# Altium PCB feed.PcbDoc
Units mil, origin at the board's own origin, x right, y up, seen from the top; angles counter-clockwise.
Board outline 1181.1 x 1181.1 mil, 2 copper layers (Top Layer, Bottom Layer); 26 components, 20 nets, 79 pads, 14 vias.
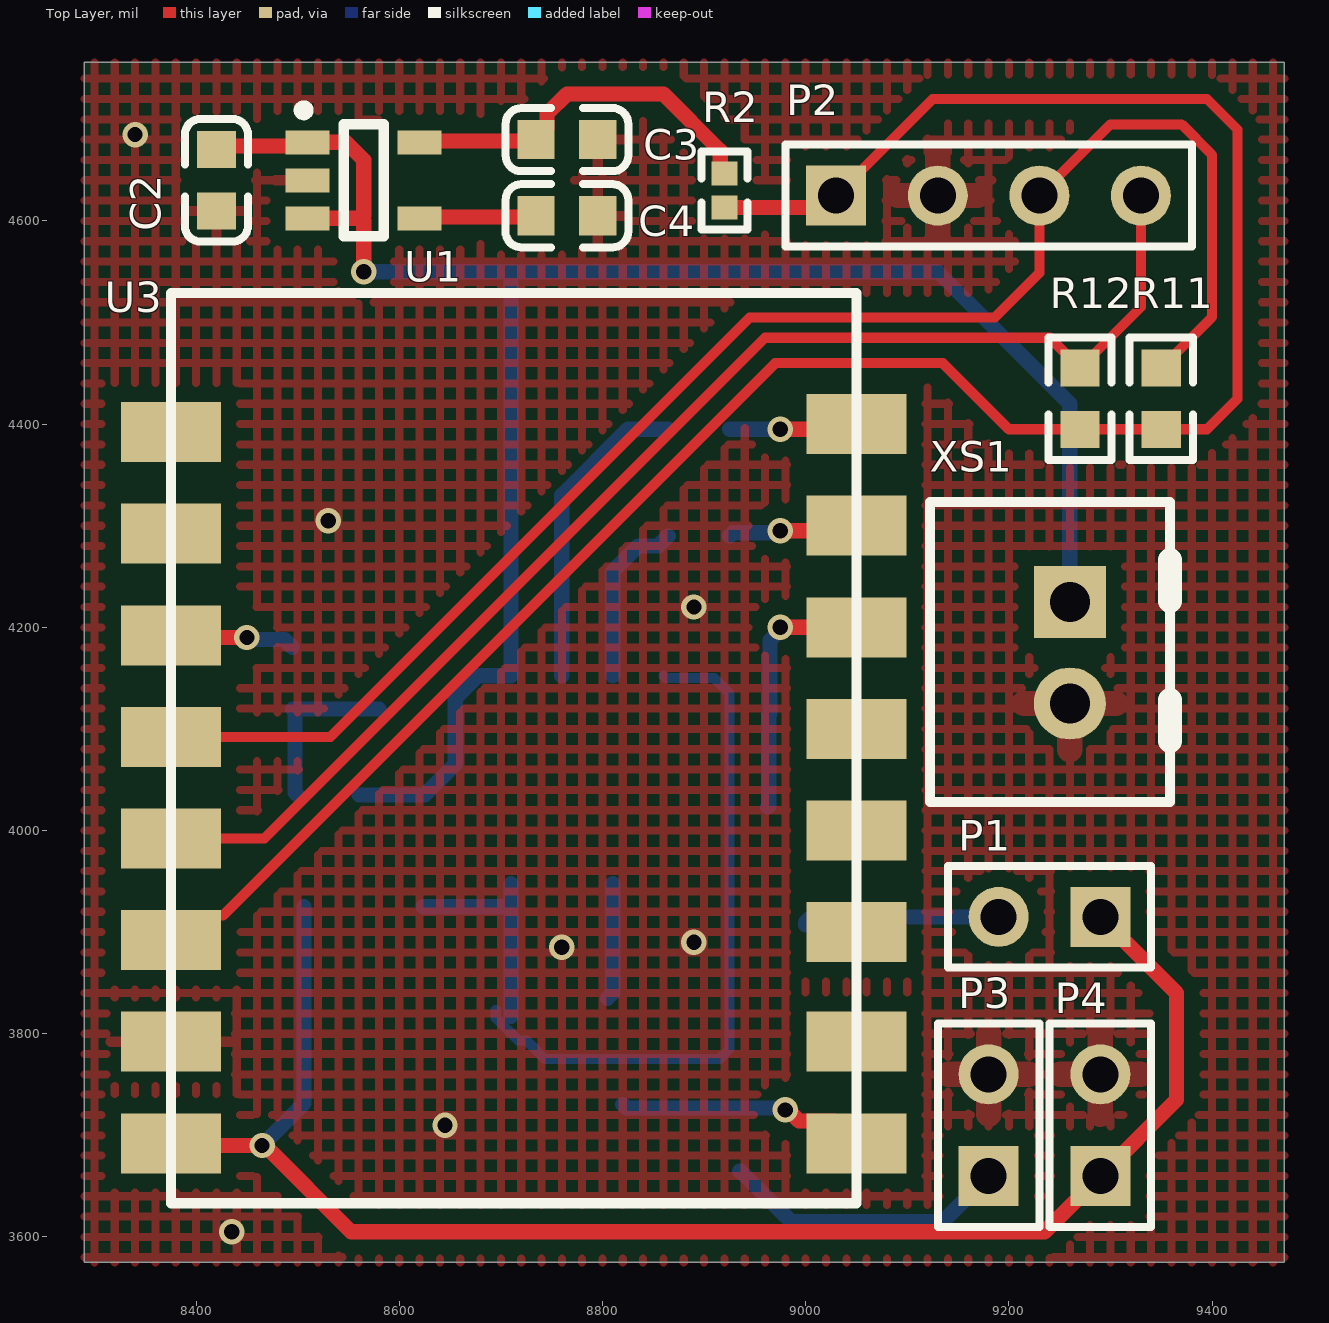
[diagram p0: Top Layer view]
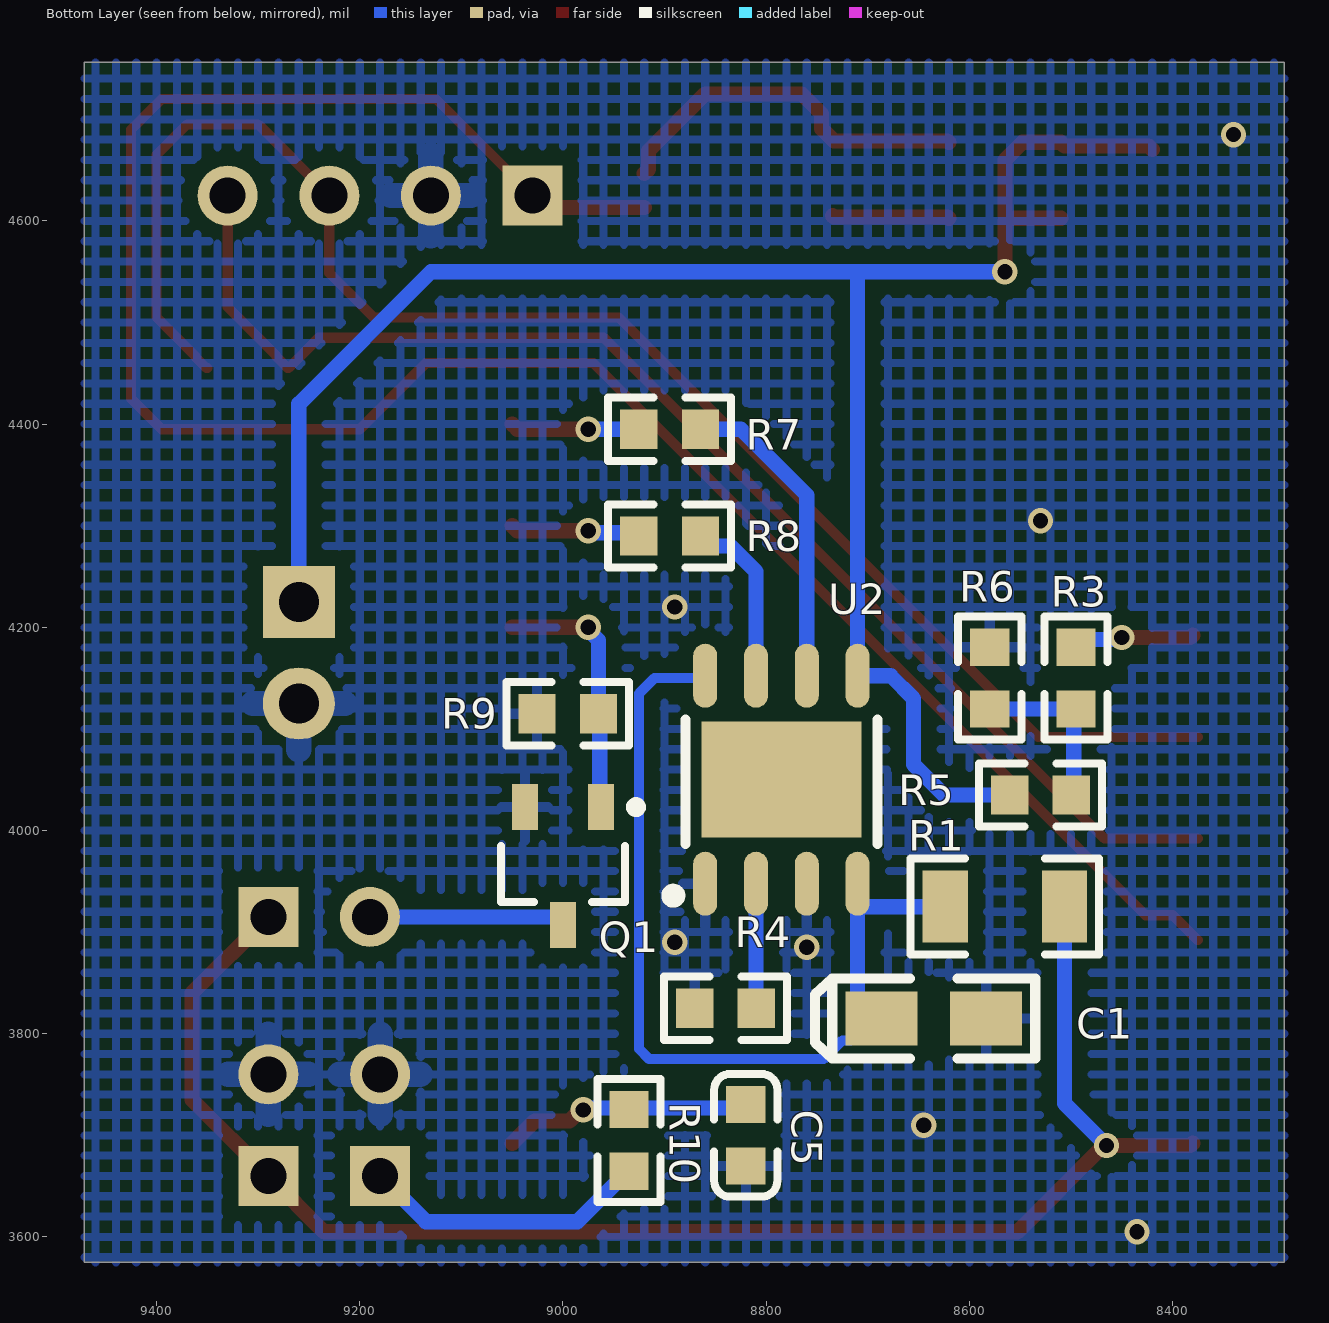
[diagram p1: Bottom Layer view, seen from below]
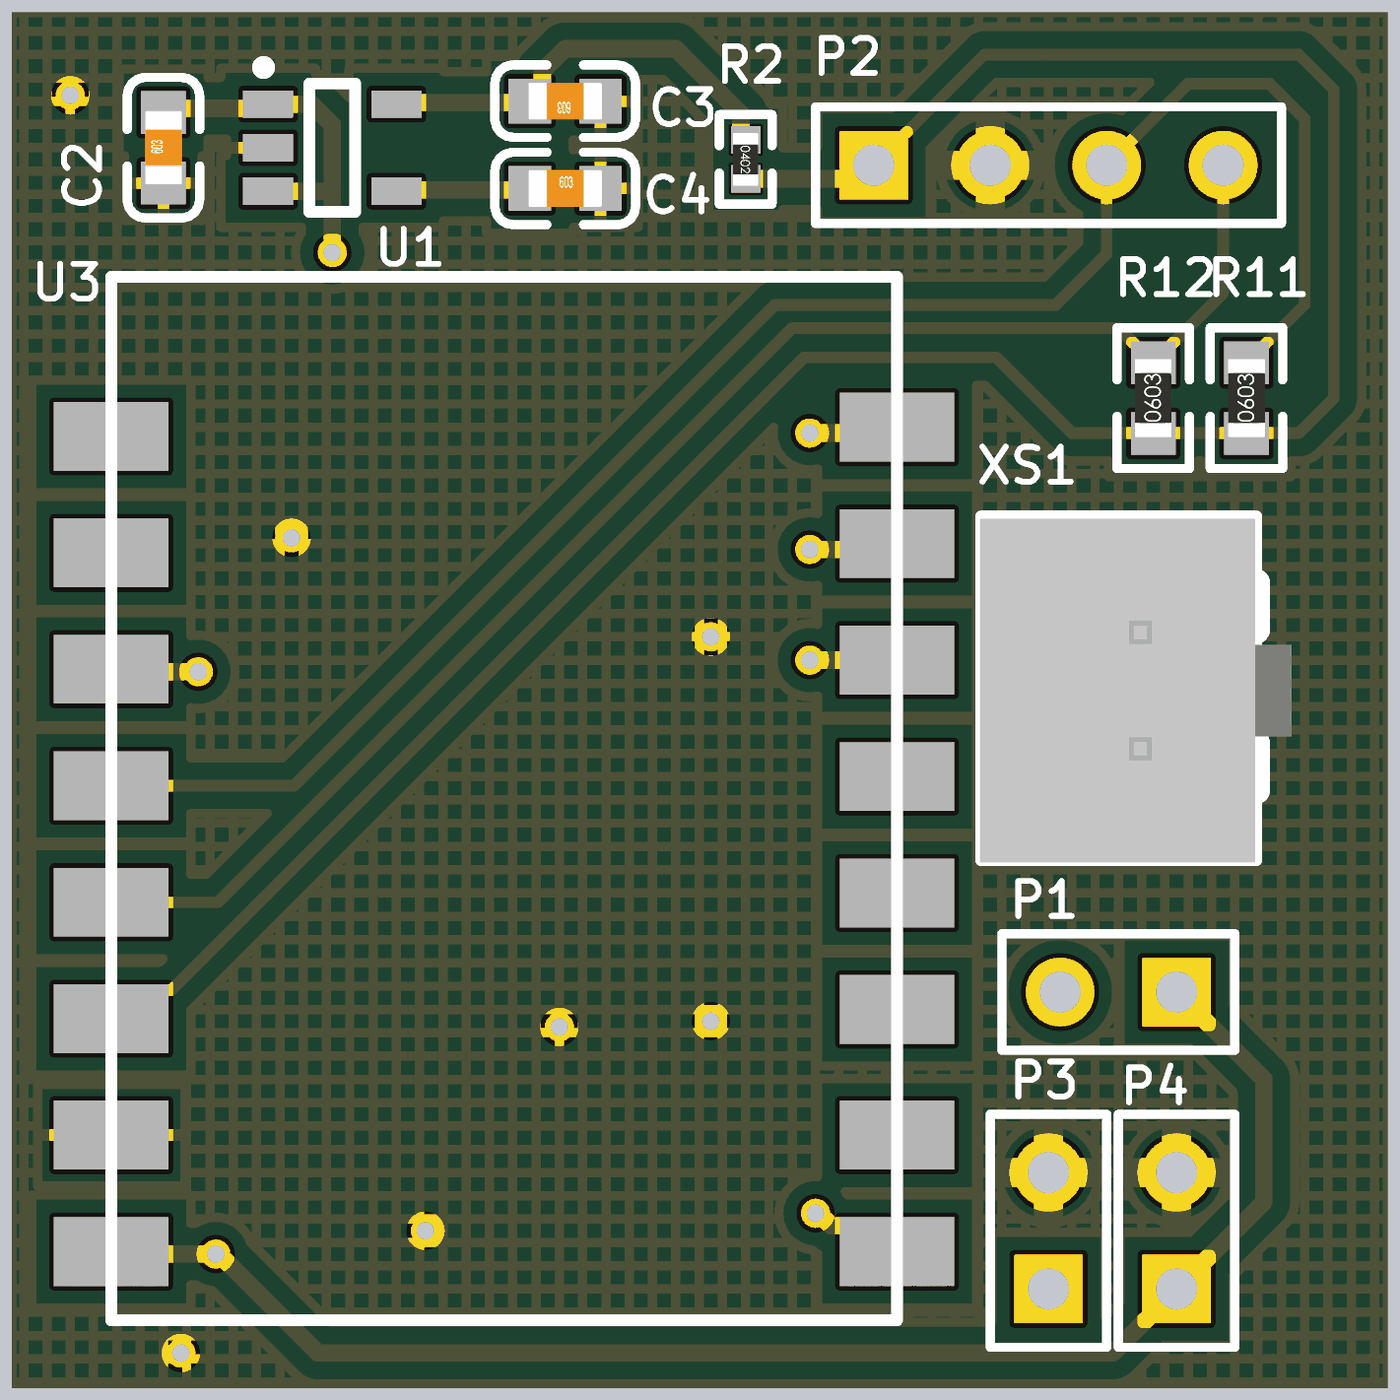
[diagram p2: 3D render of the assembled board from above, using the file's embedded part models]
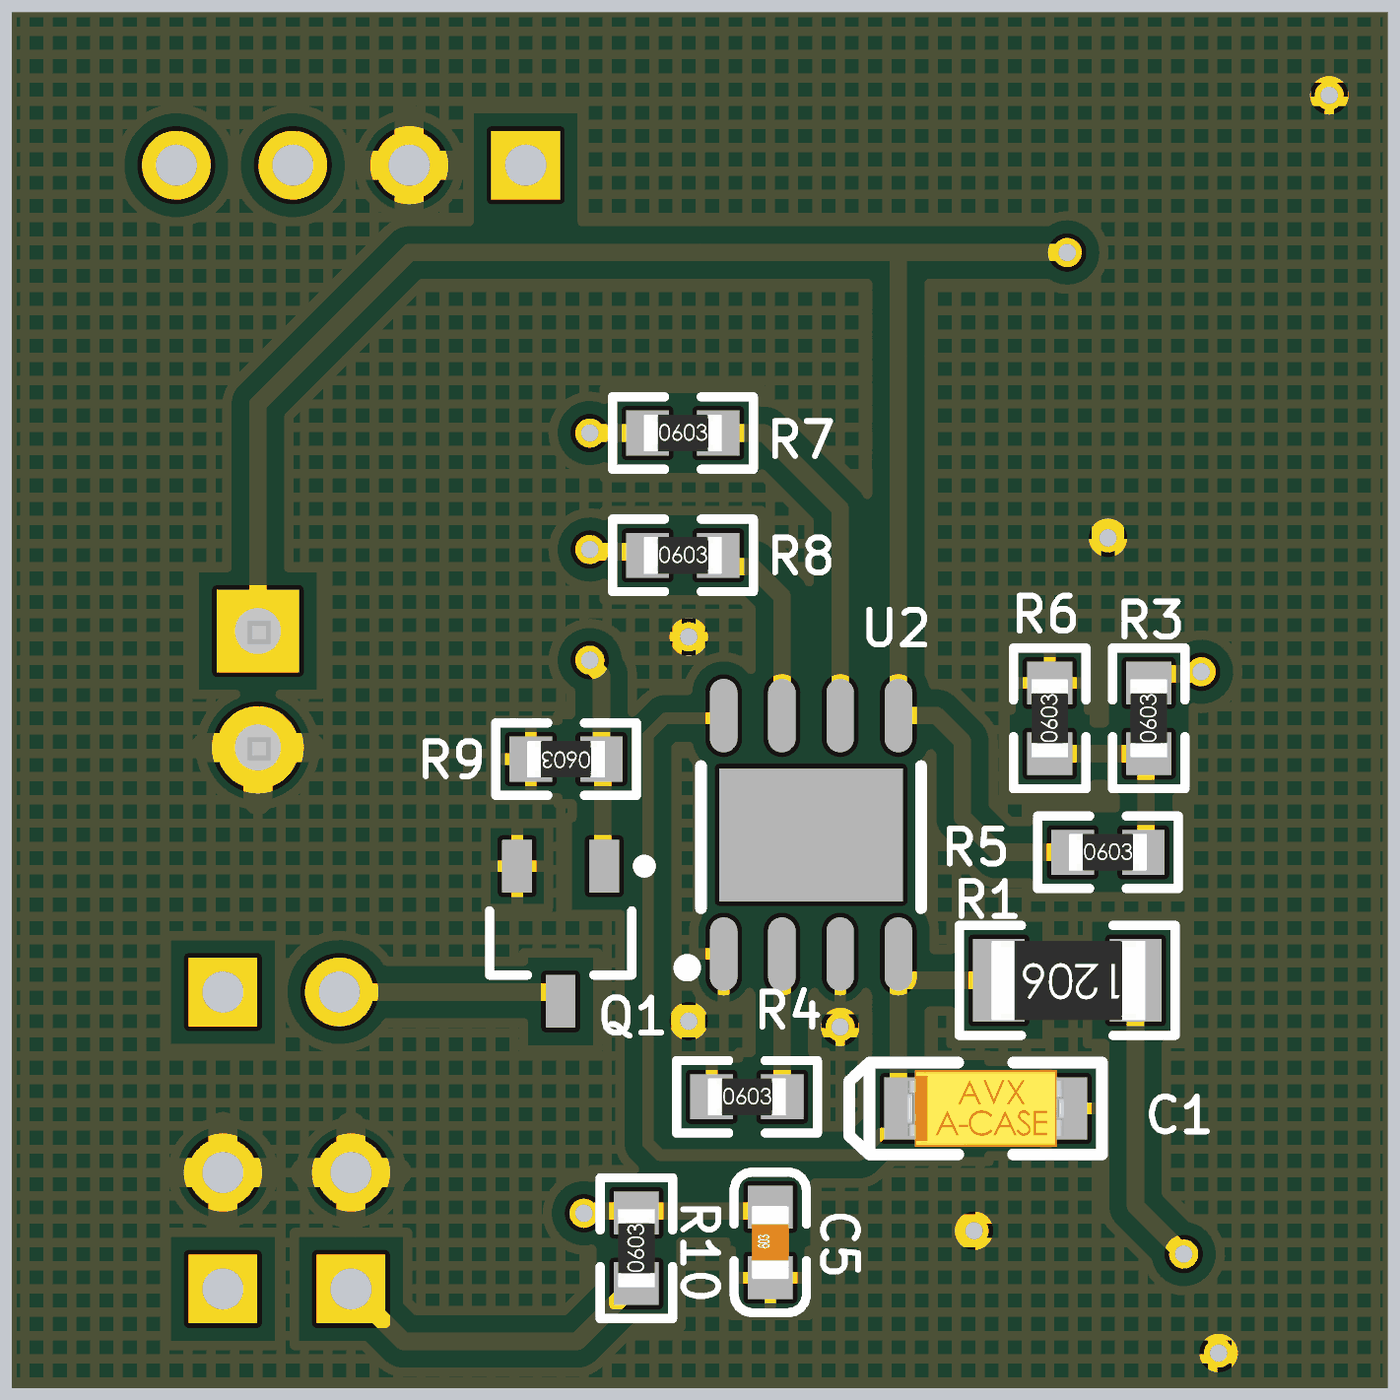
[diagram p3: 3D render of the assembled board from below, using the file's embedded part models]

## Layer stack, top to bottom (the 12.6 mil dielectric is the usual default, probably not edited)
Top Solder: solder mask 0.4, Solder Resist, Dk 3.5
Top Layer: signal copper 1.4
Dielectric 1: dielectric 12.6, FR-4, Dk 4.8
Bottom Layer: signal copper 1.4
Bottom Solder: solder mask 0.4, Solder Resist, Dk 3.5

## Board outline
8290,3575 8290,4756.1 9471.1,4756.1 9471.1,3575

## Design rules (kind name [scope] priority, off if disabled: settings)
Clearance Clearance_keep_out [INPOLYGON vs InNet('No Net') And OnLayer('Mechanical 1')] p1 off: gap=15.75 ignorepadtopadclearanceinfootprint=FALSE except(0: Arc-Hole Track-Hole SMDPad-Hole THPad-Hole Via-Hole Fill-Hole Poly-Hole Region-Hole Text-Hole)
Clearance Clearance_Copper [INPOLYGON] p2: gap=15 ignorepadtopadclearanceinfootprint=FALSE except(0: Arc-Hole Track-Hole SMDPad-Hole THPad-Hole Via-Hole Fill-Hole Poly-Hole Region-Hole Text-Hole)
Clearance [All] p3: gap=6 ignorepadtopadclearanceinfootprint=FALSE
ComponentClearance [All] p1: gap=0 collisioncheckmode=3 verticalgap=0 showdistances=FALSE
PlaneConnect [All] p1: planeconnectstyle=Relief reliefexpansion=20 reliefentries=4 reliefconductorwidth=20 reliefairgap=10
PolygonConnect PolygonConnect_power [InNet('GND')] p1 off: thpad.connectstyle=Relief thpad.reliefconductorwidth=30 thpad.reliefentries=4 thpad.polygonreliefangle="90 Angle" thpad.airgapwidth=10 smdpad.connectstyle=Relief smdpad.reliefconductorwidth=10 smdpad.reliefentries=4 smdpad.polygonreliefangle="90 Angle" smdpad.airgapwidth=10 via.connectstyle=Relief via.reliefconductorwidth=10 via.reliefentries=4 via.polygonreliefangle="90 Angle" via.airgapwidth=10
PolygonConnect [All] p2: thpad.connectstyle=Relief thpad.reliefconductorwidth=25 thpad.reliefentries=4 thpad.polygonreliefangle="90 Angle" thpad.airgapwidth=10 smdpad.connectstyle=Relief smdpad.reliefconductorwidth=10 smdpad.reliefentries=4 smdpad.polygonreliefangle="90 Angle" smdpad.airgapwidth=10 via.connectstyle=Direct via.reliefconductorwidth=10 via.reliefentries=4 via.polygonreliefangle="90 Angle" via.airgapwidth=10
PolygonConnect PolygonConnect_via [isvia] p3: connectstyle=Direct reliefconductorwidth=10 reliefentries=4 polygonreliefangle="90 Angle" airgapwidth=10
RoutingVias [All] p1: holewidth=10 width=20 viastyle="Through Hole" minholewidth=8 minwidth=15 maxholewidth=48 maxwidth=60
SolderMaskExpansion [All] p1: expansion=4 istentingtop=FALSE
Width [All] p1: maxlimit=80 minlimit=5 preferedwidth=10
28 further rules are at their usual default settings.

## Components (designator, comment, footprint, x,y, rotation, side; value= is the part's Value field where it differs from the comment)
C1 "10uF (106) ±10% 16V" CASE-A_3216 8635,3815 r0 bottom
C2 "100nF (104) 10% 50V" 0603_C 8420,4640 r90 top
C3 "10uF (106) 10% 10V" 0603_C 8765,4680 r180 top
C4 "22nF (223) 10% 50V" 0603_C 8765,4605 r0 top
C5 "100nF (104) 10% 50V" 0603_C 8820,3700 r90 bottom
P1 "Header 2" HDR1X2 9290,3915 r180 top
P2 "Header 4" HDR1X4 9030,4625 r0 top
P3 "Header 2" HDR1X2 9180,3660 r90 top
P4 "Header 2" HDR1X2 9290,3660 r90 top
Q1 "AO3400A N道沟 X0YV1T SOT-23" SOT-23-3L 9000,3965 r90 bottom
R1 "0.1Ω (R100) ±1%" 1206_R 8565,3925 r0 bottom
R2 "0Ω (0R0) ±1%" 0402_R 8920,4630 r270 top
R3 "1KΩ (1001) ±1%" 0603_R 8495,4150 r90 bottom
R4 "1.2KΩ (1201) ±1%" 0603_R 8840,3825 r180 bottom
R5 "10KΩ (1002) ±1%" 0603_R 8530,4035 r180 bottom
R6 "100KΩ (1003) ±1%" 0603_R 8580,4150 r90 bottom
R7 "510Ω (5100) ±1%" 0603_R 8895,4395 r180 bottom
R8 "510Ω (5100) ±1%" 0603_R 8895,4290 r180 bottom
R9 "10KΩ (1002) ±1%" 0603_R 8995.31,4115 r0 bottom
R10 "10KΩ (1002) ±1%" 0603_R 8935,3695 r90 bottom
R11 "1KΩ (1001) ±1%" 0603_R 9350,4425 r90 top
R12 "1KΩ (1001) ±1%" 0603_R 9270,4425 r90 top
U1 "RT9193-33" SOT-23-5 8565,4640 r180 top
U2 "TP4056" SOP-8_EP_150mil 8785,4050 r180 bottom
U3 "ESP32C3-FH4" ESP32C3-FH4 8375.2,4529.13 r0 top locked
XS1 "HA-2A" HA-2A 9260,4175 r270 top

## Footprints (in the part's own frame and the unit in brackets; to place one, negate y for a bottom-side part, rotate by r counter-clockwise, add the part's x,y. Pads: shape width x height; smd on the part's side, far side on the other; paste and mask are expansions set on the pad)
0402_R [mm]
  rect 0.6x0.65 smd mask+0.051: 1(-0.425,0) 2(0.425,0)
  silkscreen extent -0.97,-0.58 0.97,0.58, body extent -0.57,-0.27 0.58,0.28, height 0.41
0603_C [mm]
  rect 0.93x0.98 smd: 1(-0.77,0) 2(0.77,0)
  silkscreen extent -1.53,-0.79 1.54,0.79, body extent -0.8,-0.4 0.8,0.4, height 0.3
0603_R [mm]
  rect 0.93x0.98 smd: 1(-0.77,0) 2(0.77,0)
  silkscreen extent -1.53,-0.79 1.54,0.79, body extent -0.85,-0.4 0.85,0.4, height 0.56
1206_R [mm]
  rect 1.13x1.8 smd: 1(-1.49,0) 2(1.49,0)
  silkscreen extent -2.36,-1.2 2.35,1.2, body extent -1.7,-0.86 1.65,0.87, height 0.85
CASE-A_3216 [mm]
  rect 1.8x1.35 smd: 1(1.31,0) 2(-1.31,0)
  silkscreen extent -2.54,-1 2.97,1, body extent -1.7,-0.84 1.7,0.84, height 1.71
ESP32C3-FH4 [mm] "supermini 核心板"
  rect 2.5x1.5 smd: 1(0,-3.48) 2(0,-6.02) 3(0,-8.56) 4(0,-11.1) 5(0,-13.64) 6(0,-16.18) 7(0,-18.72) 8(0,-21.26) 9(17.14,-21.26) 10(17.14,-18.72) 11(17.14,-15.98) 12(17.14,-13.44) 13(17.14,-10.9) 14(17.14,-8.36) 15(17.14,-5.82) 16(17.14,-3.28)
  silkscreen extent 0,-22.76 17.14,0
HA-2A [mm]
  rect 1.8x1.8 hole 1: 1(-1.27,0)
  round 1.8 hole 1: 2(1.27,0)
  silkscreen extent -3.77,-3.5 3.73,2.5, body extent -3.72,-3.53 3.78,3.27, height 7.5
HDR1X2 [mm] "Connector; Header; 2 Position"
  rect 1.5x1.5 hole 0.9: 1(0,0)
  round 1.5 hole 0.9: 2(2.54,0)
  silkscreen extent -1.27,-1.27 3.81,1.27
HDR1X4 [mm] "Connector; Header; 4 Position"
  rect 1.5x1.5 hole 0.9: 1(0,0)
  round 1.5 hole 0.9: 2(2.54,0) 3(5.08,0) 4(7.62,0)
  silkscreen extent -1.27,-1.27 8.89,1.27
SOP-8_EP_150mil [mm]
  rect 4x2.9 smd: 0(0,0)
  oval 0.6x1.6 smd: 1(-1.905,-2.6) 2(-0.635,-2.6) 3(0.635,-2.6) 4(1.905,-2.6) 5(1.905,2.6) 6(0.635,2.6) 7(-0.635,2.6) 8(-1.905,2.6)
  silkscreen extent -2.85,-3.05 2.4,1.5
SOT-23-3L [mm] "http://www.aosmd.com/res/packaging_information/SOT-23-3L.pdf"
  rect 1.15x0.65 smd: 1(1.475,-0.95) 2(1.475,0.95) 3(-1.475,0)
  silkscreen extent -0.9,-1.95 1.6,1.55, body extent -0.9,-1.55 0.9,1.55, height 1.25
SOT-23-5 [mm]
  rect 1.1x0.6 smd: 1(1.4,-0.95) 2(1.4,0) 3(1.4,0.95) 4(-1.4,0.95) 5(-1.4,-0.95)
  silkscreen extent -0.5,-1.87 1.62,1.4

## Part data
C1: library part "3216 10uF (106) 10% 16V", "钽电容", Package=3216, SuppliersPartNumber=C7171
C2 C5: library part "0603 100nF (104) 10% 50V", "贴片电容", Package=0603, SuppliersPartNumber=C14663
C3: library part "0603 10uF (106) 10% 10V", "贴片电容", Package=0603, SuppliersPartNumber=C19702
C4: library part "0603 22nF (223) 10% 50V", "贴片电容", Package=0603, SuppliersPartNumber=C21122
P1 P3 P4: "Header, 2-Pin"
P2: "Header, 4-Pin"
Q1: "MOS(场效应管)", Package=SOT-23, SuppliersPartNumber=C20917
R1: library part "1206 0.1Ω (R100) 1%", "贴片电阻", Package=1206, SuppliersPartNumber=C25334
R2: library part "0402 0Ω (0R0) 1%", "贴片电阻", Package=0402, SuppliersPartNumber=C17168
R3 R11 R12: library part "0603 1KΩ (1001) 1%", "贴片电阻", Package=0603, SuppliersPartNumber=C21190
R4: library part "0603 1.2KΩ (1201) 1%", "贴片电阻", Package=0603, SuppliersPartNumber=C22765
R5 R9 R10: library part "0603 10KΩ (1002) 1%", "贴片电阻", Package=0603, SuppliersPartNumber=C25804
R6: library part "0603 100KΩ (1003) 1%", "贴片电阻", Package=0603, SuppliersPartNumber=C25803
R7 R8: library part "0603 510Ω (5100) 1%", "贴片电阻", Package=0603, SuppliersPartNumber=C23193
U1: "3.3V超低压差LDO"
U2: library part TP4056_[C16581], "电池电源管理", Package=SOP-8_EP_150mil, SuppliersPartNumber=C16581
U3: "ESP32C3-FH4 内置4Mflash supermini核心板"
XS1: "HA-2A 白色"

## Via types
v1: diameter 25, hole 15, Top Layer to Bottom Layer, 14 vias

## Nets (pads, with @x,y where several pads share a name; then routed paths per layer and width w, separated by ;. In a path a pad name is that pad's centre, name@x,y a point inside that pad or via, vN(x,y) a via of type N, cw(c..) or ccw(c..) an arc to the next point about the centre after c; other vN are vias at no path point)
3.3V: P2.1 R2.2 R11.1 R12.1 U3.6 | length 2151
  Top Layer w10: U3.6 8399.72,3916.65 8426.65,3916.65 8970,4460 9135,4460 9200,4395 9270,4395 9350,4395 9395,4395 9425,4425 9425,4690 9395,4720 9125,4720 P2.1
  Top Layer w15: R2.2 9018.27,4613.27 P2.1
3.3VB: C3.2 R2.1 U1.5 | length 371.3
  Top Layer w15: U1.5 8621.42,4678.7 8733.39,4678.7 8745.49,4690.81 8745.49,4705.49 8765,4725 8860,4725 8915.92,4669.08 8915.92,4650.81 R2.1
+5: P1.1 P4.1 R1.1 U3.8 | length 1537.9
  Top Layer w15: U3.8@8380.2,3692.13 8382.32,3690 8467.71,3690 8552.71,3605 9235,3605 P4.1 9365,3735 9365,3840 P1.1
  Bottom Layer w15: v1(8465,3690) 8506.34,3731.34 R1.1
ADC: R3.2 U3.3 | length 119.7
  Top Layer w15: U3.3@8380.2,4192.13 8382.32,4190 v1(8450,4190)
  Bottom Layer w15: v1(8450,4190) 8451.91,4188.09 8487.23,4188.09 R3.2
Battey: C2.2 R5.1 U1.1 U1.3 U2.5 XS1.1 | length 1896.5
  Top Layer w15: C2.2 8423.54,4673.86 8506.34,4673.86 U1.1 8547.6,4677.4 8565,4660 8565,4605 8562.6,4602.6 ; U1.3 8562.6,4602.6 ; v1(8565,4550) 8565,4600.2 8562.6,4602.6
  Bottom Layer w15: R5.1 8625,4035 8655,4065 8655,4130 8677.36,4152.36 U2.5 8710,4548.79 ; v1(8565,4550) 8710,4550 9130,4550 9260,4420 XS1.1
CHRG: R8.2 U2.7 | length 171.8
  Bottom Layer w15: U2.7 8810,4255 8835.13,4280.13 8854.82,4280.13 R8.2
GND: C1.2 C2.1 C3.1 C4.2 C5.1 P2.2 P3.2 P4.2 Q1.2 R4.1 R6.2 R9.2 U1.2 U2.1 U2.3 U3.7 XS1.2 | length 12.2
  Bottom Layer w15: R9.2 R9.2@9034.24,4106.39
  other v1: 8435,3605 8645,3710 8760,3885 8890,3890 8890,4220 8530,4305 8340,4685
NetC1_1: C1.1 R1.2 U2.4 U2.8 | length 900.4
  Bottom Layer w10: C1.1@8695,3823.43 8695,3815.43 8717.01,3793.43 8725,3793.43 8743.43,3775 8915,3775 8925,3785 8925,4135 8910,4150 8862.36,4150 U2.8
  Bottom Layer w15: R1.2 8704.71,3925 U2.4@8710,3930.29 ; C1.1@8710,3816.85 U2.4@8710,3930.29 ; U2.4 U2.4@8710,3930.29
NetC4_1: C4.1 U1.4 | length 115.6
  Top Layer w15: U1.4 8621.32,4603.8 8733.48,4603.8 C4.1
NetC5_2: C5.2 R10.2 U3.9 | length 245.8
  Top Layer w15: v1(8980,3725) 8982.71,3725 8993.55,3714.15 9027.97,3714.15 U3.9
  Bottom Layer w15: C5.2 8823.4,3726.91 8978.09,3726.91 v1(8980,3725)
NetP1_2: P1.2 Q1.3 | length 206.9
  Top Layer w15: P1.2@9178.08,3915 P1.2
  Bottom Layer w15: Q1.3 9000,3909.7 9005.3,3915 P1.2
NetP3_1: P3.1 R10.1 | length 284.2
  Bottom Layer w15: R10.1 8935.98,3664.69 8985.67,3615 9135,3615 P3.1
NetQ1_1: Q1.1 R9.1 U3.14 | length 257.1
  Top Layer w15: v1(8975,4200) U3.14
  Bottom Layer w15: Q1.1 8963.8,4024.27 8963.8,4113.8 R9.1 8965,4187.29 8975,4197.29 v1(8975,4200)
NetR3_1: R3.1 R5.2 R6.1 | length 171.6
  Bottom Layer w15: R5.2 8497.34,4037.34 8497.34,4117.34 R3.1 R6.1
NetR4_2: R4.2 U2.2 | length 114.7
  Bottom Layer w15: R4.2@8805,3835 8810,3840 U2.2
NetR7_1: R7.1 U3.16 | length 126.8
  Top Layer w15: v1(8975,4395) 9045,4395 U3.16
  Bottom Layer w15: R7.1 v1(8975,4395)
NetR8_1: R8.1 U3.15 | length 128.8
  Top Layer w15: v1(8975,4295) 9045,4295 U3.15
  Bottom Layer w15: R8.1 8928.4,4293.09 8973.09,4293.09 v1(8975,4295)
SCL: P2.3 R11.2 U3.4 | length 1562.6
  Top Layer w10: U3.4 8532.13,4092.13 8945,4505 9186.21,4505 9230,4548.79 P2.3 9300,4695 9370,4695 9400,4665 9400,4505.32 9361.79,4467.11 9361.79,4466.12 9350.98,4455.32 R11.2
SDA: P2.4 R12.2 U3.5 | length 1306.4
  Top Layer w10: U3.5 8467.13,3992.13 8960,4485 9240.32,4485 R12.2 9270.98,4455.32 9281.79,4466.12 9281.79,4467.11 9330,4515.32 P2.4
STDBY: R7.2 U2.6 | length 309.2
  Bottom Layer w15: U2.6 8760,4330 8825,4395 R7.2
pads on no net: U2.0 U3.1 U3.2 U3.10 U3.11 U3.12 U3.13

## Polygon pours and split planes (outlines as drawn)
GND on Top Layer "GND_L01_P000" (hatched 90Degree grid 20 track 8, remove dead copper, pour order 0): 8290,3575 9471.1,3575 9471.1,4756.1 8290,4756.1
GND on Bottom Layer "GND_L02_P001" (hatched 90Degree grid 20 track 8, remove dead copper, pour order 1): 8290,3575 9471.1,3575 9471.1,4756.1 8290,4756.1

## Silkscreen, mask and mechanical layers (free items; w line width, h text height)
Mechanical 1:
  the board outline again, w10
